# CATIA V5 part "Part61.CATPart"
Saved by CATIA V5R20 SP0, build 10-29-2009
Part number: 9FA 042212
Revision: ANY
Definition: UNKNOWN
Nomenclature: 9FA 042212
Source: Unknown
Bounding box of the stored display mesh (mm): x -2 to 2, y 0.1 to 12.1, z -2 to 2
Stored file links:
  C:\Users\Utente\Desktop\IO LAVORO\3D X SITO CF\CUMSA\3D files FA\FA 042212-21\Part61.CATPart

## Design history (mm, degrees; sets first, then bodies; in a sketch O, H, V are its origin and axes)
Set1 "FacciaKO#NONE#3374"
  DatumSurface1 "Sup3374_1"
  DatumCurve1 "Crv3374_1"
Body1 "Cortar-Extruir3" (main body)
  Solid1: solid without history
